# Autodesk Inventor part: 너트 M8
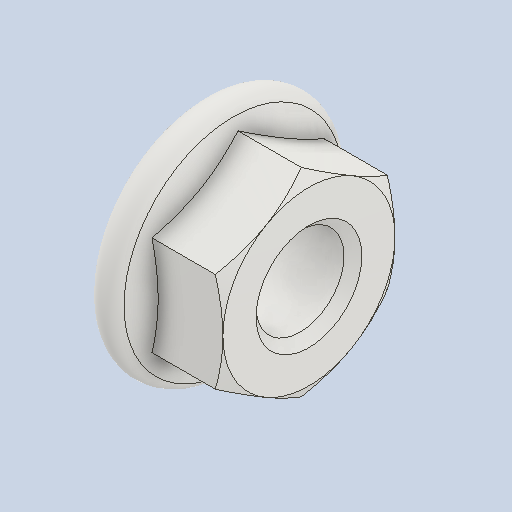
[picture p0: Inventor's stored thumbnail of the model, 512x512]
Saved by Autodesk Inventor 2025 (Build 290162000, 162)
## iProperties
Created: 2024-07
Part Number: 너트 M8
Material: 스테인리스강
Description: 플랜지붙이 6각 너트 - 일반 스레드
Document SubType Name: Modeling
Designer: deana
Density: 8 g/cm^3
Appearance: 기본값
Author: jhkim
Sending System: Autodesk Inventor 2025
Preprocessor: ST-DEVELOPER v20
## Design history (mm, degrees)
feature "Solid1"
node "솔리드1"
